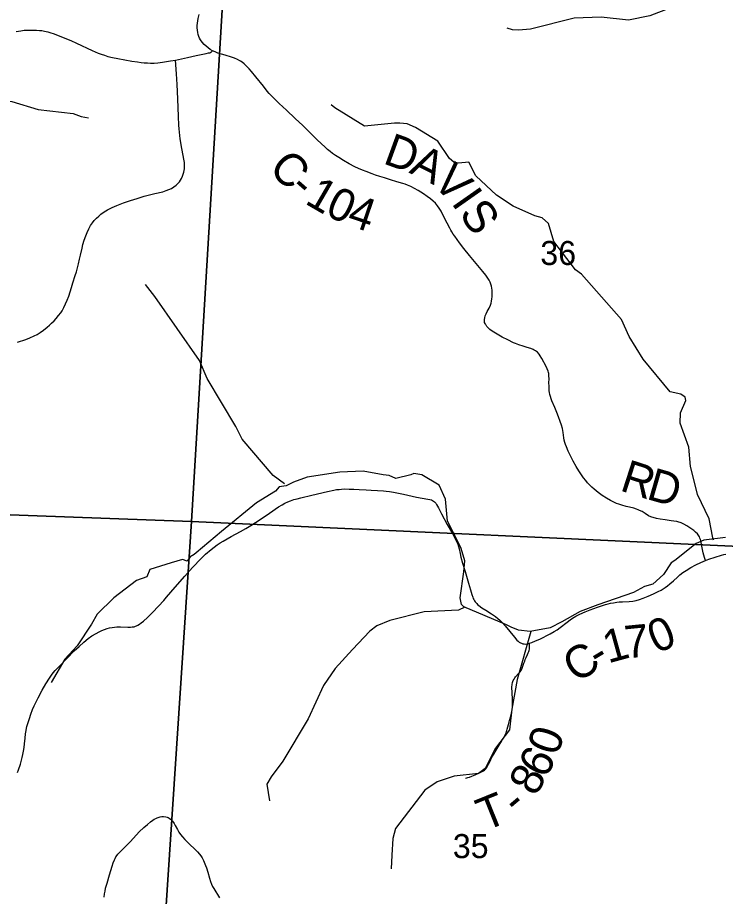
# Model space of a CAD drawing. Extents: x 0 to 34, y 0 to 22.
# Drawn here: x 6.952 to 8.185, y 17.604 to 19.136 of the extents above; entities that cross this region are included whole.
import ezdxf

# ---------------------------------------------------------------- set-up
doc = ezdxf.new("R2010")
doc.units = 0
for name, color, linetype in [('GM_X_County_Road', 7, 'Continuous'), ('GM_X_County_Road_Text', 7, 'Continuous'), ('GM_X_Minor_River', 7, 'Continuous'), ('GM_X_Section', 7, 'Continuous'), ('GM_X_Section_Text', 7, 'Continuous'), ('GM_X_Township_Road', 7, 'Continuous'), ('GM_X_Township_Road_Text', 7, 'Continuous')]:
    doc.layers.add(name, color=color, linetype=linetype)

msp = doc.modelspace()

# ---------------------------------------------------------------- linework, layer by layer
at = {"layer": 'GM_X_County_Road'}
for points in [[(7.34, 19.0595), (7.3391, 19.0601), (7.3348, 19.0625), (7.3298, 19.0648), (7.3245, 19.0668), (7.3137, 19.0703), (7.3007, 19.0739), (7.2959, 19.0757), (7.2915, 19.0775), (7.2874, 19.08), (7.2836, 19.0827), (7.2801, 19.0856), (7.277, 19.0886), (7.2733, 19.0927), (7.2703, 19.0969), (7.2687, 19.0997), (7.2675, 19.1028), (7.2664, 19.1063), (7.2656, 19.1099), (7.2651, 19.1139), (7.2649, 19.1178), (7.2649, 19.1218), (7.2652, 19.1259), (7.2657, 19.1299), (7.2665, 19.1342), (7.2682, 19.1411)], [(8.1506, 18.1896), (8.1489, 18.1947), (8.1466, 18.2028), (8.1448, 18.2114), (8.1425, 18.2234), (8.1419, 18.226), (8.141, 18.2282), (8.1401, 18.2304), (8.1391, 18.2321), (8.1378, 18.234), (8.1365, 18.2357), (8.1334, 18.2388), (8.1301, 18.2415), (8.1251, 18.2453), (8.1184, 18.2497), (8.113, 18.2528), (8.1084, 18.2549), (8.1063, 18.2557), (8.1043, 18.2563), (8.1006, 18.2571), (8.0957, 18.2579), (8.0908, 18.2586), (8.0804, 18.26), (8.0719, 18.2613), (8.0653, 18.2625), (8.0594, 18.264), (8.0573, 18.2647), (8.0554, 18.2655), (8.0516, 18.2674), (8.0454, 18.2714), (8.0401, 18.2745), (8.0358, 18.2767), (8.0331, 18.2779), (8.0306, 18.2788), (8.0259, 18.2803), (8.0181, 18.2822), (8.0127, 18.2835), (8.0049, 18.2856), (7.9998, 18.2873), (7.9957, 18.2889), (7.992, 18.2905), (7.985, 18.2941), (7.978, 18.2982), (7.9708, 18.3028), (7.9638, 18.3078), (7.9565, 18.3135), (7.9523, 18.3173), (7.949, 18.3205), (7.9453, 18.3245), (7.9419, 18.3285), (7.9383, 18.3333), (7.9344, 18.3389), (7.9301, 18.3456), (7.9253, 18.3532), (7.9202, 18.3624), (7.9153, 18.372), (7.9113, 18.3801), (7.9082, 18.3876), (7.9067, 18.3914), (7.9055, 18.3949), (7.9046, 18.399), (7.904, 18.4029), (7.9026, 18.4127), (7.9013, 18.4192), (7.8997, 18.4253), (7.8975, 18.4319), (7.8947, 18.4395), (7.8915, 18.4475), (7.8879, 18.4561), (7.883, 18.4679), (7.8819, 18.4712), (7.8806, 18.475), (7.8796, 18.4788), (7.8789, 18.482), (7.8784, 18.4852), (7.8781, 18.4889), (7.8781, 18.4932), (7.8779, 18.499), (7.878, 18.5059), (7.8778, 18.5115), (7.8775, 18.5152), (7.8771, 18.5173), (7.8765, 18.5196), (7.875, 18.5236), (7.8732, 18.5275), (7.8655, 18.5416), (7.8628, 18.546), (7.8607, 18.5488), (7.8577, 18.5522), (7.856, 18.5535), (7.8544, 18.5548), (7.8523, 18.5561), (7.8504, 18.5571), (7.8461, 18.5588), (7.8398, 18.5608), (7.8329, 18.563), (7.8255, 18.5653), (7.8198, 18.5673), (7.8158, 18.569), (7.8059, 18.5738), (7.7965, 18.5786), (7.7847, 18.5854), (7.7786, 18.5892), (7.7747, 18.5921), (7.7719, 18.5948), (7.7697, 18.5972), (7.7682, 18.5993), (7.7671, 18.6009), (7.7664, 18.6025), (7.7656, 18.6042), (7.7652, 18.6061), (7.7653, 18.6076), (7.7653, 18.6092), (7.7658, 18.6123), (7.7668, 18.6158), (7.7682, 18.6192), (7.7702, 18.6231), (7.7736, 18.6292), (7.7757, 18.6343), (7.777, 18.6379), (7.7778, 18.6415), (7.7785, 18.6453), (7.7789, 18.6487), (7.7791, 18.6536), (7.7791, 18.6573), (7.7788, 18.6607), (7.7783, 18.664), (7.7777, 18.6675), (7.7767, 18.6711), (7.7751, 18.6747), (7.7735, 18.678), (7.7715, 18.6813), (7.7679, 18.6866), (7.7628, 18.693), (7.7393, 18.7211), (7.7295, 18.7334), (7.722, 18.7433), (7.7137, 18.7549), (7.7111, 18.7584), (7.7088, 18.7621), (7.7068, 18.7653), (7.705, 18.7684), (7.7004, 18.7772), (7.693, 18.7921), (7.6899, 18.7982), (7.6867, 18.8036), (7.6838, 18.8077), (7.6801, 18.812), (7.676, 18.8159), (7.6712, 18.8199), (7.6658, 18.824), (7.6591, 18.8285), (7.6496, 18.8345), (7.6436, 18.8378), (7.6369, 18.8412), (7.6312, 18.8436), (7.6272, 18.8451), (7.623, 18.8466), (7.6129, 18.8496), (7.6017, 18.853), (7.591, 18.8562), (7.5832, 18.8587), (7.5757, 18.8612), (7.5699, 18.8632), (7.5595, 18.8672), (7.5526, 18.8699), (7.546, 18.8727), (7.5396, 18.8757), (7.5296, 18.8809), (7.5199, 18.8864), (7.5115, 18.8916), (7.5058, 18.8953), (7.5006, 18.8989), (7.4963, 18.9021), (7.4921, 18.9055), (7.4884, 18.909), (7.4803, 18.9166), (7.4745, 18.9222), (7.4629, 18.9334), (7.4486, 18.9473), (7.4356, 18.9597), (7.4203, 18.974), (7.4078, 18.986), (7.3994, 18.994), (7.3938, 18.9997), (7.3902, 19.0035), (7.3868, 19.0074), (7.38, 19.0162), (7.3669, 19.0326), (7.3596, 19.0416), (7.3552, 19.0466), (7.3507, 19.0512), (7.3463, 19.055), (7.3428, 19.0577), (7.34, 19.0595)], [(6.9515, 17.82), (6.9532, 17.8244), (6.9565, 17.8346), (6.9596, 17.8461), (6.9608, 17.851), (6.962, 17.8569), (6.9629, 17.8632), (6.9638, 17.87), (6.9648, 17.8794), (6.9656, 17.8871), (6.9663, 17.8929), (6.9671, 17.8968), (6.9678, 17.9001), (6.9698, 17.9067), (6.9722, 17.9138), (6.9747, 17.9212), (6.9779, 17.9298), (6.9804, 17.936), (6.9838, 17.9427), (6.9873, 17.9498), (6.9944, 17.9632), (7.001, 17.9744), (7.0073, 17.9844), (7.0105, 17.9892), (7.0138, 17.9935), (7.0174, 17.9977), (7.024, 18.0047), (7.0375, 18.0188), (7.0501, 18.0317), (7.0587, 18.0397), (7.0671, 18.047), (7.0748, 18.0533), (7.0812, 18.0578), (7.0885, 18.0623), (7.0936, 18.065), (7.0984, 18.0672), (7.103, 18.069), (7.1075, 18.0706), (7.1118, 18.0719), (7.1162, 18.0728), (7.1203, 18.0733), (7.1246, 18.0736), (7.1312, 18.0736), (7.1436, 18.0732), (7.1484, 18.0732), (7.1516, 18.0735), (7.1547, 18.074), (7.1569, 18.0747), (7.1591, 18.0756), (7.1614, 18.0768), (7.1642, 18.0784), (7.1671, 18.0805), (7.1709, 18.0836), (7.1779, 18.0902), (7.1867, 18.0988), (7.1973, 18.1098), (7.2064, 18.1198), (7.2113, 18.1255), (7.2263, 18.1429), (7.243, 18.1621), (7.2567, 18.1773), (7.2718, 18.1929), (7.2794, 18.2002), (7.2888, 18.2083), (7.294, 18.2125), (7.2994, 18.2165), (7.3047, 18.2199), (7.31, 18.2231), (7.3242, 18.231), (7.3402, 18.2398), (7.3495, 18.2451), (7.3583, 18.2505), (7.3742, 18.261), (7.3905, 18.2719), (7.4065, 18.2828), (7.4128, 18.2865), (7.4176, 18.2891), (7.4225, 18.2915), (7.4274, 18.2934), (7.4333, 18.2954), (7.4387, 18.2969), (7.4454, 18.2985), (7.4648, 18.3033), (7.4916, 18.3097), (7.5028, 18.312), (7.5076, 18.3128), (7.512, 18.3133), (7.5165, 18.3138), (7.5212, 18.314), (7.5295, 18.3138), (7.5375, 18.3134), (7.5471, 18.3128), (7.5593, 18.3123), (7.5679, 18.3118), (7.5787, 18.3112), (7.5894, 18.3106), (7.5943, 18.3102), (7.6001, 18.3095), (7.6067, 18.3085), (7.6243, 18.305), (7.6469, 18.3), (7.6668, 18.2964), (7.6701, 18.2956), (7.6729, 18.2948), (7.6749, 18.294), (7.6767, 18.2928), (7.6786, 18.2914), (7.6804, 18.2893), (7.6821, 18.2868), (7.6838, 18.2841), (7.6855, 18.2809), (7.6905, 18.2707), (7.7007, 18.2523), (7.7097, 18.2363), (7.7129, 18.2305), (7.7155, 18.2254), (7.7174, 18.2213), (7.7188, 18.2176), (7.72, 18.2135), (7.7211, 18.2094), (7.7228, 18.2016), (7.7245, 18.195), (7.7274, 18.1849), (7.7318, 18.1704), (7.7377, 18.1498), (7.7412, 18.138), (7.7434, 18.1303), (7.7452, 18.1252), (7.7459, 18.1231), (7.7469, 18.1211), (7.748, 18.1192), (7.7492, 18.1174), (7.7504, 18.1159), (7.7519, 18.1143), (7.7535, 18.1127), (7.7556, 18.111), (7.7611, 18.107), (7.7677, 18.1027), (7.7779, 18.0962), (7.7845, 18.0917), (7.7889, 18.0883), (7.7921, 18.0855), (7.7965, 18.0812), (7.8018, 18.0752), (7.8175, 18.0559), (7.8221, 18.0507), (7.8243, 18.0487), (7.8262, 18.0471), (7.8281, 18.0459), (7.8299, 18.0451), (7.8324, 18.0443), (7.8349, 18.0438), (7.8376, 18.0437), (7.8408, 18.0442), (7.8442, 18.045), (7.8481, 18.0464), (7.8546, 18.0492), (7.8618, 18.0524), (7.8801, 18.0617), (7.8867, 18.0653), (7.892, 18.0686), (7.8976, 18.0725), (7.9094, 18.0818), (7.9148, 18.0859), (7.9189, 18.0887), (7.9246, 18.0922), (7.9317, 18.0959), (7.9407, 18.1), (7.9494, 18.1034), (7.9622, 18.108), (7.9763, 18.1127), (7.9811, 18.114), (7.9854, 18.1149), (7.9901, 18.1158), (7.9962, 18.1167), (8.0005, 18.1171), (8.0061, 18.1175), (8.0179, 18.1177), (8.0242, 18.1184), (8.0297, 18.1195), (8.0358, 18.1212), (8.0422, 18.1235), (8.0509, 18.1272), (8.0599, 18.1312), (8.0684, 18.1352), (8.0737, 18.1379), (8.0768, 18.1397), (8.0803, 18.142), (8.0844, 18.1451), (8.0887, 18.1487), (8.0948, 18.1541), (8.1017, 18.1605), (8.1062, 18.1644), (8.1111, 18.1682), (8.1168, 18.1719), (8.125, 18.1769), (8.1338, 18.1817), (8.1423, 18.1859), (8.1506, 18.1896), (8.1567, 18.1919), (8.1675, 18.1954), (8.1784, 18.1985), (8.1824, 18.1995), (8.1863, 18.2002)], [(7.1028, 17.6027), (7.1033, 17.6081), (7.1041, 17.6131), (7.1051, 17.6181), (7.1076, 17.6271), (7.1118, 17.6414), (7.1164, 17.6565), (7.1184, 17.6626), (7.1203, 17.6673), (7.1216, 17.6699), (7.1231, 17.6727), (7.125, 17.6756), (7.1266, 17.6777), (7.1291, 17.6804), (7.1394, 17.6904), (7.1454, 17.6966), (7.1484, 17.6998), (7.1636, 17.7162), (7.1717, 17.724), (7.1778, 17.7294), (7.1833, 17.7339), (7.1873, 17.7368), (7.1899, 17.7384), (7.1926, 17.7398), (7.1952, 17.741), (7.1982, 17.7421), (7.2004, 17.7426), (7.2031, 17.743), (7.2062, 17.7431), (7.2101, 17.7426), (7.2122, 17.742), (7.2141, 17.7411), (7.216, 17.74), (7.2184, 17.7383), (7.22, 17.7368), (7.2218, 17.7349), (7.2243, 17.7312), (7.2264, 17.7275), (7.2303, 17.7203), (7.2328, 17.716), (7.2355, 17.7119), (7.2388, 17.7075), (7.2429, 17.703), (7.2519, 17.6945), (7.2601, 17.6868), (7.2654, 17.6815), (7.269, 17.6772), (7.2711, 17.6746), (7.2733, 17.6712), (7.2757, 17.6665), (7.2794, 17.6579), (7.281, 17.6535), (7.2833, 17.6462), (7.2862, 17.6357), (7.2879, 17.63), (7.2896, 17.6254), (7.2914, 17.6213), (7.2935, 17.6177), (7.3037, 17.6015)]]:
    msp.add_lwpolyline(points, dxfattribs=at)
at = {"layer": 'GM_X_Minor_River'}
for points in [[(8.3531, 19.3781), (8.2909, 19.3769), (8.2632, 19.3688), (8.1857, 19.3236), (8.1655, 19.3044), (8.1395, 19.2768), (8.1319, 19.2639), (8.1187, 19.2138), (8.1056, 19.1732), (8.1003, 19.1622), (8.0888, 19.1521), (8.0539, 19.139), (8.0163, 19.1309), (7.9686, 19.1365), (7.9216, 19.1345), (7.8457, 19.1152), (7.8248, 19.1135), (7.8142, 19.1143), (7.8051, 19.117)], [(6.6593, 19.0751), (6.6921, 19.0842), (6.7353, 19.0745), (6.7889, 19.0462), (6.8244, 19.0211), (6.8696, 19.0022), (6.9414, 18.9893), (6.9875, 18.9753), (7.0485, 18.9684), (7.0623, 18.9634), (7.0755, 18.9607)], [(8.1649, 18.2249), (8.1634, 18.2286), (8.1572, 18.2618), (8.137, 18.3046), (8.1302, 18.3307), (8.1248, 18.3529), (8.1217, 18.3871), (8.1064, 18.429), (8.1069, 18.4465), (8.1162, 18.4682), (8.1153, 18.4739), (8.1075, 18.4791), (8.0891, 18.4835), (8.0421, 18.5404), (8.0176, 18.5799), (8.0041, 18.6092), (7.9343, 18.6882), (7.9239, 18.6961), (7.8865, 18.7455), (7.8773, 18.7769), (7.8658, 18.7864), (7.8535, 18.7902), (7.8154, 18.807), (7.7865, 18.8262), (7.7501, 18.86), (7.7384, 18.8835), (7.7202, 18.8818), (7.7123, 18.8836), (7.7046, 18.8903), (7.6839, 18.9202), (7.6453, 18.9442), (7.6308, 18.9504), (7.618, 18.9519), (7.6089, 18.9515), (7.5566, 18.9463), (7.5046, 18.9783), (7.4983, 18.9835)], [(7.4171, 18.3231), (7.3971, 18.3374), (7.3431, 18.401), (7.332, 18.423), (7.282, 18.5066), (7.2686, 18.5378), (7.1907, 18.6493), (7.1747, 18.6703)], [(8.1858, 18.2295), (8.148, 18.2249), (8.1344, 18.2188), (8.0973, 18.1894), (8.0909, 18.1852), (8.0777, 18.1647), (8.0588, 18.1483), (8.0441, 18.1441), (8.0252, 18.1338), (7.9628, 18.112), (7.9322, 18.1005), (7.9005, 18.0822), (7.8801, 18.0722), (7.8449, 18.0653), (7.8249, 18.0679), (7.812, 18.0732), (7.8041, 18.0774), (7.7292, 18.1088), (7.7254, 18.1129), (7.7232, 18.1243), (7.7295, 18.1696), (7.731, 18.1886), (7.725, 18.2102), (7.706, 18.2478), (7.7011, 18.2581), (7.6973, 18.2961), (7.6863, 18.3207), (7.6561, 18.3385), (7.6424, 18.3408), (7.6371, 18.3389), (7.6111, 18.332), (7.5993, 18.3376), (7.5891, 18.3388), (7.554, 18.3448), (7.5135, 18.3435), (7.4561, 18.3347), (7.4323, 18.3259), (7.4198, 18.3194), (7.4073, 18.3178), (7.4009, 18.3102), (7.368, 18.2896), (7.3072, 18.2401), (7.263, 18.2027), (7.2596, 18.1997), (7.2525, 18.1955), (7.2475, 18.1879), (7.2392, 18.1909), (7.2196, 18.1851), (7.1822, 18.1736), (7.1769, 18.1607), (7.1587, 18.1546), (7.1195, 18.1245), (7.0904, 18.0959), (7.0806, 18.0784), (7.0556, 18.0407), (7.0341, 18.0171), (7.0103, 17.9764)], [(7.7312, 18.1079), (7.7204, 18.1026), (7.6601, 18.0996), (7.6005, 18.0848), (7.5781, 18.0754), (7.5655, 18.066), (7.5354, 18.0342), (7.5053, 18.001), (7.4847, 17.9715), (7.4582, 17.9135), (7.4142, 17.8393), (7.3936, 17.812), (7.3859, 17.7992), (7.3907, 17.7702)], [(7.8461, 18.0655), (7.8225, 17.9821), (7.813, 17.9303), (7.8093, 17.894), (7.7849, 17.8621), (7.7668, 17.8267), (7.7548, 17.8183), (7.7127, 17.8132), (7.6829, 17.8035), (7.6613, 17.789), (7.6105, 17.7223), (7.6055, 17.7046), (7.6042, 17.6758), (7.6027, 17.6519)]]:
    msp.add_lwpolyline(points, dxfattribs=at)
at = {"layer": 'GM_X_Section'}
for points in [[(6.2595, 19.3129), (7.3152, 19.2658), (7.2546, 18.2574), (6.1942, 18.2962)], [(8.3558, 19.2156), (8.299, 18.2095), (7.2546, 18.2574), (7.3152, 19.2658)], [(6.1942, 18.2962), (7.2546, 18.2574), (7.1862, 17.219), (6.1312, 17.2799)], [(8.299, 18.2095), (8.2333, 17.168), (7.1862, 17.219), (7.2546, 18.2574)]]:
    msp.add_lwpolyline(points, close=True, dxfattribs=at)
at = {"layer": 'GM_X_Township_Road'}
for points in [[(6.9493, 19.1115), (6.957, 19.1127), (6.963, 19.1135), (6.9692, 19.1139), (6.9745, 19.114), (6.9798, 19.1139), (6.9847, 19.1138), (6.9897, 19.1134), (6.9939, 19.1129), (6.9988, 19.112), (7.0042, 19.1107), (7.0093, 19.1093), (7.0138, 19.1078), (7.021, 19.1051), (7.034, 19.0998), (7.0442, 19.0955), (7.0546, 19.0911), (7.0816, 19.0783), (7.0921, 19.0739), (7.0976, 19.0718), (7.1031, 19.0699), (7.1092, 19.0681), (7.1173, 19.0661), (7.1266, 19.0641), (7.1505, 19.0599), (7.1609, 19.0583), (7.1668, 19.0576), (7.1725, 19.057), (7.1782, 19.0565), (7.1834, 19.0562), (7.1895, 19.0563), (7.1961, 19.0568), (7.2045, 19.0579), (7.2179, 19.06), (7.2268, 19.0616)], [(6.9512, 18.57), (6.966, 18.5748), (6.9729, 18.5774), (6.9803, 18.5807), (6.9858, 18.5835), (6.9911, 18.5868), (6.9966, 18.5908), (7.0034, 18.5963), (7.0072, 18.5995), (7.0109, 18.6029), (7.0151, 18.6071), (7.0191, 18.6113), (7.0231, 18.6161), (7.0269, 18.621), (7.0292, 18.6246), (7.0325, 18.6306), (7.0354, 18.6368), (7.0381, 18.6432), (7.0407, 18.6503), (7.0458, 18.6654), (7.0482, 18.6731), (7.0522, 18.6861), (7.0541, 18.6926), (7.0578, 18.7063), (7.0598, 18.7147), (7.0613, 18.7213), (7.0641, 18.734), (7.0655, 18.7401), (7.0678, 18.7478), (7.0704, 18.7554), (7.0727, 18.7612), (7.0757, 18.7674), (7.079, 18.7733), (7.0821, 18.778), (7.0852, 18.7819), (7.0889, 18.786), (7.093, 18.7898), (7.0969, 18.7929), (7.1025, 18.7968), (7.1084, 18.8003), (7.1167, 18.8045), (7.1247, 18.808), (7.1363, 18.8125), (7.1486, 18.8169), (7.1598, 18.8205), (7.1724, 18.8241), (7.1911, 18.8288), (7.2049, 18.8322), (7.2109, 18.834), (7.2155, 18.8358), (7.2199, 18.838), (7.2242, 18.8407), (7.2281, 18.8437), (7.231, 18.8465), (7.2337, 18.8494), (7.2354, 18.852), (7.2373, 18.8552), (7.239, 18.859), (7.2404, 18.863), (7.2413, 18.8664), (7.2419, 18.8694), (7.2423, 18.872), (7.2426, 18.8746), (7.2427, 18.8773), (7.2426, 18.8799), (7.2424, 18.8831), (7.242, 18.886), (7.2381, 18.9072), (7.2351, 18.9241), (7.2343, 18.9303), (7.2336, 18.9362), (7.2331, 18.942), (7.2328, 18.9479), (7.2321, 18.963), (7.2308, 18.9939), (7.2295, 19.0189), (7.2285, 19.0375), (7.2268, 19.0616), (7.2372, 19.0637), (7.248, 19.0662), (7.263, 19.0695), (7.2801, 19.073), (7.2846, 19.074), (7.2865, 19.0745), (7.2883, 19.0752), (7.2899, 19.076), (7.2915, 19.0775)], [(7.7325, 17.8101), (7.7346, 17.8104), (7.7366, 17.811), (7.7391, 17.8117), (7.7504, 17.8162), (7.7557, 17.8185), (7.7603, 17.8207), (7.7637, 17.8225), (7.7654, 17.8237), (7.7673, 17.8256), (7.7694, 17.8285), (7.7725, 17.8342), (7.7746, 17.8384), (7.7785, 17.8466), (7.7815, 17.8516), (7.784, 17.8558), (7.7875, 17.8617), (7.7911, 17.8674), (7.7941, 17.8721), (7.797, 17.8772), (7.7989, 17.8805), (7.801, 17.8845), (7.803, 17.8891), (7.8037, 17.891), (7.8043, 17.8932), (7.805, 17.8955), (7.8072, 17.9033), (7.8092, 17.9103), (7.8107, 17.9161), (7.8124, 17.923), (7.8131, 17.9263), (7.8137, 17.9297), (7.8141, 17.9336), (7.8143, 17.9378), (7.8143, 17.9408), (7.8144, 17.9448), (7.8135, 17.9616), (7.8132, 17.9654), (7.8132, 17.9688), (7.8137, 17.9731), (7.8145, 17.9767), (7.8157, 17.98), (7.817, 17.9826), (7.8183, 17.9847), (7.8198, 17.9866), (7.825, 17.9921), (7.8266, 17.9941), (7.8277, 17.9954), (7.8289, 17.9972), (7.8298, 17.9989), (7.8313, 18.0018), (7.8342, 18.0103), (7.8355, 18.014), (7.8366, 18.017), (7.838, 18.0201), (7.8406, 18.0252), (7.8418, 18.0281), (7.8428, 18.0306), (7.8435, 18.0327), (7.844, 18.0349), (7.8442, 18.0376), (7.8442, 18.045)]]:
    msp.add_lwpolyline(points, dxfattribs=at)

# ---------------------------------------------------------------- texts
at = {"layer": 'GM_X_County_Road_Text'}
for s, rotation, p in [('D', 340.0016, (7.5868, 18.8821)), ('A', 333.7917, (7.6323, 18.8657)), ('C', 315.2926, (7.3873, 18.8703)), ('V', 314.687, (7.6731, 18.8465)), ('-', 318.6757, (7.4231, 18.8349)), ('1', 329.9072, (7.4505, 18.8125)), ('0', 334.9905, (7.4856, 18.7924)), ('I', 305.0173, (7.7066, 18.8129)), ('4', 341.0668, (7.5235, 18.7751)), ('S', 304.5862, (7.7199, 18.7939)), ('R', 342.1118, (7.9996, 18.312)), ('D', 343.9296, (8.0459, 18.2971)), ('0', 22.8253, (8.0649, 18.0265)), ('7', 5.6189, (8.0121, 18.0185)), ('1', 15.4032, (7.9808, 18.0097)), ('C', 32.0401, (7.9252, 17.9747)), ('-', 30.8138, (7.9645, 17.9993))]:
    msp.add_text(s, height=0.0568, rotation=rotation, dxfattribs=at).set_placement(p)
at = {"layer": 'GM_X_Section_Text'}
for s, p in [('36', (7.8628, 18.7044)), ('35', (7.7103, 17.6706))]:
    msp.add_text(s, height=0.04186, rotation=0, dxfattribs=at).set_placement(p)
at = {"layer": 'GM_X_Township_Road_Text'}
for s, rotation, p in [('0', 70.935, (7.8924, 17.8474)), ('6', 61.4261, (7.8715, 17.8072)), ('8', 62.0232, (7.8552, 17.7765)), ('T', 21.8814, (7.7663, 17.7172)), ('-', 39.982, (7.8224, 17.7431))]:
    msp.add_text(s, height=0.0568, rotation=rotation, dxfattribs=at).set_placement(p)

doc.saveas('drawing.dxf')
